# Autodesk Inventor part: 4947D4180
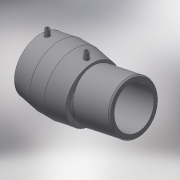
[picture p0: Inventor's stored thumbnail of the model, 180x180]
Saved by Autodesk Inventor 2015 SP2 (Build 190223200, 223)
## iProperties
Created: 2017-06
Part Number: 4947D4180
Material: Generic
Description: PLASSON ADJUSTABLE ELBOW (ONE SIDE) 180
Document SubType Name: Modeling
Designer: KIM
Mass: 55.0731 g
Surface Area: 148.067 cm^2
Volume: 55.0731 cm^3
Density: 1 g/cm^3
Appearance: Default
Author: KIM
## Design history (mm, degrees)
derived "4947D4.ipt"
feature "Solid1::4947D4.ipt"
tag "TaggingFeature1"
body "Solid1"
other parameters: "d0" = 191.625, "d2" = 223, "d3" = 138, "d4" = 69, "d5" = 200.7, "d8" = 168 deg, "d10" = 55.2, "d11" = 18.4, "d29" = 128, "d30" = 15, "d31" = 73, "d34" = 5 deg, "d41" = 4, "d42" = 14, "d43" = 0, "d48" = 162, "d55" = 32.175, "d57" = 168 deg, "d62" = 3, "d63" = 0, "d65" = 365, "d67" = 162, "d68" = 135 deg, "d69" = 138, "d70" = 82.51, "d71" = 4.46, "L_" = 365, "L_1" = 138, "D_" = 223, "A_" = 128, "d_2" = 12, "L_0" = 148, "L_2" = 138, "d54" = 53.625, "d59" = 206.43096
